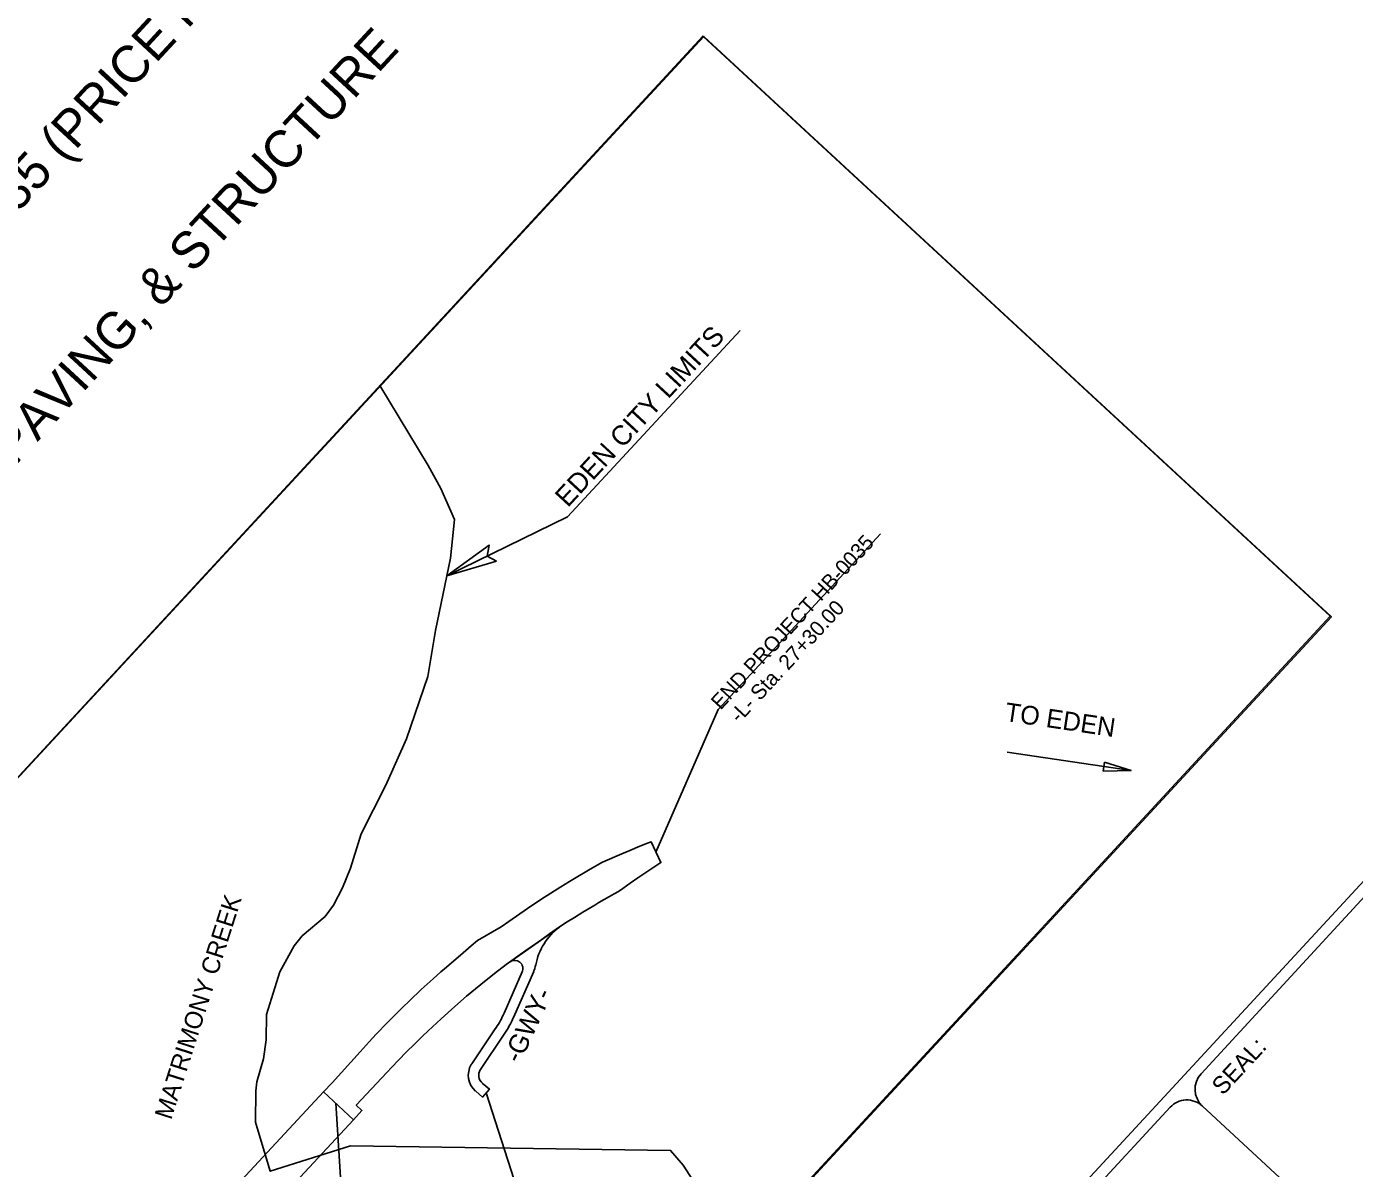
# Model space of a CAD drawing. Extents: x 1766669 to 1770980, y 998119 to 1002502.
# Drawn here: x 1768756 to 1770036, y 1000271 to 1001372 of the extents above; entities that cross this region are included whole.
import ezdxf

# ---------------------------------------------------------------- set-up
doc = ezdxf.new("R2010")
doc.units = 0
for name, color, linetype in [('_CIVIL_CONSTRUCTION', 7, 'Continuous'), ('Default Symbol CELL', 7, 'Continuous'), ('Exist Control Text', 7, 'Continuous'), ('Exist Hydro Stream or Body of Water', 7, 'Continuous'), ('Exist Roads Text', 7, 'Continuous'), ('Exist Structure Major Deck Tunnel Box Culvert', 7, 'Continuous'), ('Exist Survey Setup Group', 7, 'Continuous'), ('Exist Utilities Power Pole CELL', 7, 'Continuous')]:
    doc.layers.add(name, color=color, linetype=linetype)

msp = doc.modelspace()

# ---------------------------------------------------------------- linework, layer by layer
at = {"layer": 'Default Symbol CELL'}
for p, q in [((1768227.4, 998581.1), (1770560.1, 1001104.7)), ((1769277.9, 1000898.8), (1769444.3, 1001078.6)), ((1769161.6, 1000842), (1769277.9, 1000898.8)), ((1769888.6, 1000361.9), (1770181.4, 1000679.7)), ((1769821.2, 1000654.2), (1769701.6, 1000671.9)), ((1769471.1, 999910.2), (1769858.8, 1000329.6)), ((1770148, 1000092.2), (1769889.9, 1000330.8))]:
    msp.add_line(p, q, dxfattribs=at)
msp.add_lwpolyline([(1769795.6, 1000662.4), (1769821.2, 1000654.2), (1769794.3, 1000653.7)], close=True, dxfattribs=at)
for centre, start, end in [((1769904.8, 1000347), 137.2512, 227.2512), ((1769874.9, 1000314.7), 47.2512, 137.2512)]:
    msp.add_arc(centre, 22, start, end, dxfattribs=at)
at = {"layer": 'Exist Control Text'}
for p, q in [((1769222.5, 1000470), (1769270.1, 1000503.4)), ((1769216.7, 1000420.4), (1769234.2, 1000460.1)), ((1769245.3, 1000460.4), (1769225.8, 1000416.3))]:
    msp.add_line(p, q, dxfattribs=at)
msp.add_lwpolyline([(1769050.9, 1000353.3), (1769042.7, 1000344.5), (1769071.7, 1000317.6), (1769079.8, 1000326.4), (1769074.3, 1000331.5), (1769103.8, 1000363.1), (1769108.5, 1000368.2), (1769115.1, 1000375.1), (1769122.8, 1000383), (1769130.4, 1000390.6), (1769138.1, 1000398.1), (1769143.5, 1000403.3), (1769156.1, 1000415), (1769169.4, 1000426.9), (1769180.7, 1000436.7), (1769194.4, 1000448.1), (1769207.4, 1000458.5), (1769218.7, 1000467.2), (1769224.1, 1000471.1), (1769229.9, 1000475.2), (1769237.7, 1000480.7), (1769244, 1000485.1), (1769253.1, 1000491.5), (1769260.7, 1000496.9), (1769270.1, 1000503.5), (1769277.7, 1000508.3), (1769284.6, 1000512.7), (1769292.7, 1000517.7), (1769304.2, 1000524.6), (1769308.1, 1000526.9), (1769318.3, 1000532.9), (1769322.8, 1000535.4), (1769327.1, 1000537.8), (1769331.1, 1000540.7), (1769338.4, 1000545.8), (1769345.6, 1000550.8), (1769367.9, 1000565.6), (1769358.5, 1000585.6), (1769355, 1000584.2), (1769347.6, 1000581.3), (1769338, 1000577.3), (1769330.3, 1000574), (1769311.6, 1000565.8), (1769304.4, 1000561.8), (1769298.1, 1000558.2), (1769286.1, 1000551.2), (1769279.7, 1000547.3), (1769271.4, 1000542.2), (1769252.3, 1000530), (1769239.3, 1000521.3), (1769221.3, 1000508.8), (1769214, 1000503.5), (1769191.2, 1000490.4), (1769185.1, 1000485.2), (1769174.6, 1000476.2), (1769159.3, 1000463.1), (1769155.9, 1000460.2), (1769148.3, 1000453.4), (1769137, 1000443.1), (1769125.9, 1000432.6), (1769118.6, 1000425.5), (1769104.2, 1000411.1), (1769093.6, 1000400.1), (1769086.7, 1000392.6), (1769078, 1000383.1), (1769068.9, 1000373)], close=True, dxfattribs=at)
for points in [[(1769185.2, 1000370.8), (1769185.7, 1000371.6), (1769207.6, 1000404.2), (1769209.1, 1000406.4)], [(1769216.9, 1000400.1), (1769194, 1000366.1), (1769193.8, 1000365.7)], [(1769195.8, 1000352.8), (1769202.6, 1000347.1), (1769196.1, 1000339.5), (1769189.4, 1000345.2)]]:
    msp.add_lwpolyline(points, dxfattribs=at)
for centre, radius, start, end in [((1769306.2, 1000455.5), 60, 126.985, 169.1181), ((1769226.9, 1000463.3), 8, 336.2191, 123.1968), ((1769217.8, 1000472.5), 30, 336.2191, 349.1181), ((1769129.8, 1000458.7), 95, 326.6105, 336.2191), ((1769129.8, 1000458.7), 105, 326.0729, 336.2191), ((1769202.3, 1000360.5), 20, 148.9617, 229.7157), ((1769202.3, 1000360.5), 10, 148.1968, 229.7157)]:
    msp.add_arc(centre, radius, start, end, dxfattribs=at)
at = {"layer": 'Exist Hydro Stream or Body of Water'}
msp.add_lwpolyline([(1769096.9, 1001025.6), (1769143.6, 1000948.4), (1769155.7, 1000926.2), (1769168.9, 1000896.4), (1769165.1, 1000859), (1769150.7, 1000789.2), (1769143.4, 1000744.9), (1769122.6, 1000684.9), (1769102.7, 1000640.2), (1769078.9, 1000593.4), (1769068.7, 1000560.1), (1769061, 1000541.2), (1769052.4, 1000524.6), (1769044.3, 1000513.5), (1769022, 1000494.9), (1769014.3, 1000485.2), (1769000.6, 1000460.2), (1768987.9, 1000419), (1768987.3, 1000394.5), (1768984.7, 1000376.2), (1768978.3, 1000354.2), (1768977.4, 1000345.6), (1768977.3, 1000315.1), (1768991.4, 1000267.9), (1769068.6, 1000292.3), (1769377.3, 1000288), (1769389.3, 1000273.7), (1769413.2, 1000236.8)], dxfattribs=at)
at = {"layer": 'Exist Roads Text'}
msp.add_lwpolyline([(1769042.7, 1000344.5), (1769071.7, 1000317.6), (1768921.9, 1000156.4), (1768893, 1000183.3)], close=True, dxfattribs=at)
at = {"layer": 'Exist Structure Major Deck Tunnel Box Culvert'}
msp.add_lwpolyline([(1769209.6, 1000856), (1769161.6, 1000842), (1769202.3, 1000871.6), (1769200.5, 1000861)], close=True, dxfattribs=at)
at = {"layer": 'Exist Survey Setup Group'}
for points in [[(1768011.1, 999850.8), (1769408.2, 1001362.3), (1770013.2, 1000803.1), (1768616, 999291.6)], [(1768011.1, 999850.8), (1769409.4, 1001362), (1770014.3, 1000802.4), (1768615.9, 999291.1)]]:
    msp.add_lwpolyline(points, close=True, dxfattribs=at)
at = {"layer": 'Exist Utilities Power Pole CELL'}
for p, q in [((1769423.2, 1000713.1), (1769579.7, 1000882.4)), ((1769423.2, 1000713.1), (1769363.2, 1000575.6)), ((1769054.5, 1000333.6), (1769069, 1000108.5)), ((1769264.6, 1000141.2), (1769199.4, 1000343.7))]:
    msp.add_line(p, q, dxfattribs=at)

# ---------------------------------------------------------------- texts
at = {"layer": '_CIVIL_CONSTRUCTION'}
msp.add_text('MATRIMONY CREEK', height=17.094, rotation=72.3441, dxfattribs=at).set_placement((1768895.8, 1000316.8))
at = {"layer": 'Default Symbol CELL'}
for s, height, rotation, p in [('LOCATION: REPLACE BRIDGE #780177 ON SR 1535 (PRICE RD) OVER', 35.736, 47.237, (1767986.5, 1000368.3)), ('TYPE OF WORK: GRADING,  DRAINAGE,  PAVING, & STRUCTURE ', 35.736, 47.237, (1768103.6, 1000253.6)), ('EDEN CITY LIMITS', 19, 47.2214, (1769278.1, 1000907.2)), ('TO EDEN', 18, 351.562, (1769698.7, 1000702.2)), ('-GWY-', 18.42, 65.2002, (1769232, 1000371.1)), ('SEAL:', 16.79, 47.237, (1769909.7, 1000340.4))]:
    msp.add_text(s, height=height, rotation=rotation, dxfattribs=at).set_placement(p)
at = {"layer": 'Exist Utilities Power Pole CELL'}
for s, p in [('END PROJECT HB-0035', (1769425.5, 1000712)), ('-L- Sta. 27+30.00', (1769443.6, 1000699.4))]:
    msp.add_text(s, height=14.543, rotation=47.2512, dxfattribs=at).set_placement(p)

doc.saveas('drawing.dxf')
